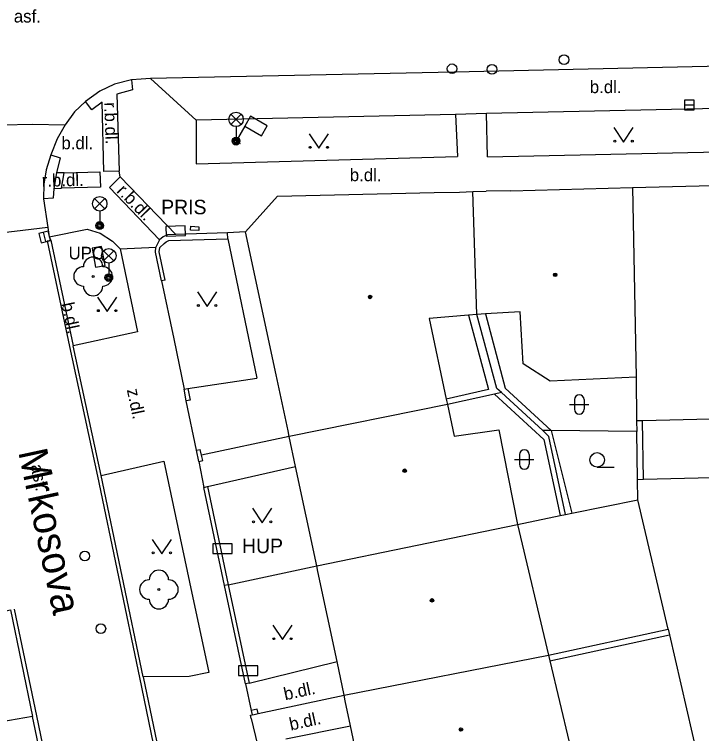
# Model space of a CAD drawing. Extents: x -596229 to -595156, y -1161237 to -1159376.
# Drawn here: x -595829.41 to -595793.88, y -1160929.68 to -1160892.51 of the extents above; entities that cross this region are included whole.
import ezdxf

# ---------------------------------------------------------------- set-up
doc = ezdxf.new("R2010")
doc.units = 0
for name, color, linetype in [('DOP - kresba z DSPS bez souradnic', 7, 'Continuous'), ('DOP - rozhrani ploch obecne', 7, 'Continuous'), ('Level 22', 7, 'Continuous'), ('Level 24', 7, 'Continuous'), ('Level 27', 7, 'Continuous'), ('Level 28', 7, 'Continuous'), ('Level 33', 7, 'Continuous'), ('Level 34', 7, 'Continuous'), ('Level 36', 7, 'Continuous'), ('Level 39', 7, 'Continuous'), ('Nazvy ulic', 7, 'Continuous'), ('silnoproud - povrch.  znaky a  RIS  skut. velikost', 7, 'Continuous'), ('slaboproud - povrch.  znaky a tel. budka skut. velikost', 7, 'Continuous'), ('Specificka linie pasportu komunikaci', 7, 'Continuous'), ('TM - budovy zdene_ betonove - VP', 7, 'Continuous'), ('TM - chodniky - VP', 7, 'Continuous'), ('TM - komunikace - VP', 7, 'Continuous'), ('TM - letecke snimky - pomocna linie', 7, 'Continuous'), ('TM - plot drateny_ kovovy - VP', 7, 'Continuous'), ('TM - podezdivka plotu - VP', 7, 'Continuous'), ('TM - pomocna konstrukcni linie', 7, 'Continuous'), ('TM - popis objektu', 7, 'Continuous'), ('TM - popis povrchu', 7, 'Continuous'), ('TM - rozhrani mezi zpev. plochami mezi sebou - VP', 7, 'Continuous'), ('TM - rozhrani ploch obecne - VP', 7, 'Continuous'), ('TM - vjezd na pozemek', 7, 'Continuous'), ('TM - vstup do budovy - zdene_ betonove', 7, 'Continuous')]:
    doc.layers.add(name, color=color, linetype=linetype)

msp = doc.modelspace()

# ---------------------------------------------------------------- linework, layer by layer
at = {"layer": 'DOP - kresba z DSPS bez souradnic'}
for points in [[(-595805.06, -1160907.99), (-595804.03, -1160911.82)], [(-595805.93, -1160908.06), (-595804.89, -1160911.89)], [(-595804.89, -1160911.89), (-595807.08, -1160912.39)], [(-595804.03, -1160911.82), (-595801.65, -1160914.02)], [(-595804.59, -1160912.13), (-595802.04, -1160914.48)], [(-595796.89, -1160916.55), (-595796.94, -1160913.51)], [(-595801.65, -1160914.02), (-595800.59, -1160918.29)], [(-595802.04, -1160914.48), (-595801.2, -1160918.41)], [(-595801.72, -1160925.91), (-595795.54, -1160924.57)]]:
    msp.add_lwpolyline(points, dxfattribs=at)
at = {"layer": 'DOP - rozhrani ploch obecne'}
for points in [[(-595804.46, -1160911.84), (-595805.5, -1160908.02)], [(-595804.23, -1160912.05), (-595804.59, -1160912.13)], [(-595804.23, -1160912.05), (-595804.46, -1160911.84)], [(-595802.09, -1160914.02), (-595804.23, -1160912.05)], [(-595804.59, -1160912.13), (-595807.02, -1160912.67)], [(-595797.24, -1160913.52), (-595797.23, -1160914.07)], [(-595801.65, -1160914.02), (-595802.09, -1160914.02)], [(-595801.77, -1160914.32), (-595802.09, -1160914.02)], [(-595800.91, -1160918.35), (-595801.77, -1160914.32)], [(-595797.23, -1160914.07), (-595801.65, -1160914.02)], [(-595797.19, -1160916.56), (-595797.23, -1160914.07)], [(-595796.89, -1160916.55), (-595797.19, -1160916.56)], [(-595797.17, -1160917.59), (-595797.19, -1160916.56)], [(-595789.82, -1160916.37), (-595796.89, -1160916.55)], [(-595800.59, -1160918.29), (-595797.17, -1160917.59)], [(-595795.61, -1160924.28), (-595797.17, -1160917.59)], [(-595803.4, -1160918.87), (-595801.2, -1160918.41)], [(-595801.2, -1160918.41), (-595800.91, -1160918.35)], [(-595800.91, -1160918.35), (-595800.59, -1160918.29)], [(-595801.79, -1160925.62), (-595795.61, -1160924.28)], [(-595795.61, -1160924.28), (-595795.54, -1160924.57)], [(-595795.54, -1160924.57), (-595794.07, -1160930.94)]]:
    msp.add_lwpolyline(points, dxfattribs=at)
at = {"layer": 'Level 22'}
for centre in [(-595825.34, -1160906.05), (-595821.94, -1160922.23)]:
    msp.add_circle(centre, 0.05, dxfattribs=at)
for centre, start, end in [((-595825.34, -1160905.55), 0, 180), ((-595825.84, -1160906.05), 90, 270), ((-595824.84, -1160906.05), 270, 90), ((-595825.34, -1160906.55), 180, 0), ((-595821.94, -1160921.73), 0, 180), ((-595822.44, -1160922.23), 90, 270), ((-595821.44, -1160922.23), 270, 90), ((-595821.94, -1160922.73), 180, 0)]:
    msp.add_arc(centre, 0.5, start, end, dxfattribs=at)
at = {"layer": 'Level 24'}
for points in [[(-595821.56, -1160903.97), (-595820.56, -1160903.93), (-595820.58, -1160903.43), (-595821.58, -1160903.47)], [(-595825.391, -1160904.585), (-595825.212, -1160905.569), (-595824.72, -1160905.48), (-595824.899, -1160904.496)], [(-595819.148, -1160920.369), (-595818.148, -1160920.369), (-595818.148, -1160919.869), (-595819.148, -1160919.869)], [(-595817.828, -1160926.669), (-595816.828, -1160926.669), (-595816.828, -1160926.169), (-595817.828, -1160926.169)]]:
    msp.add_lwpolyline(points, close=True, dxfattribs=at)
at = {"layer": 'Level 27'}
for p, q in [((-595794.76, -1160897.19), (-595794.26, -1160897.19)), ((-595827.78, -1160904.253), (-595827.9, -1160903.767))]:
    msp.add_line(p, q, dxfattribs=at)
for points in [[(-595794.76, -1160897.44), (-595794.26, -1160897.44), (-595794.26, -1160896.94), (-595794.76, -1160896.94)], [(-595827.537, -1160904.193), (-595827.657, -1160903.707), (-595828.143, -1160903.827), (-595828.023, -1160904.313)]]:
    msp.add_lwpolyline(points, close=True, dxfattribs=at)
at = {"layer": 'Level 28'}
for centre in [(-595800.99, -1160894.85), (-595806.78, -1160895.32), (-595804.72, -1160895.35), (-595825.77, -1160920.5), (-595824.94, -1160924.25)]:
    msp.add_circle(centre, 0.25, dxfattribs=at)
at = {"layer": 'Level 33'}
for p, q in [((-595818.215, -1160898.2), (-595817.685, -1160897.67)), ((-595818.215, -1160897.67), (-595817.685, -1160898.2)), ((-595817.95, -1160898.31), (-595817.95, -1160899.06)), ((-595825.265, -1160902.56), (-595824.735, -1160902.03)), ((-595825.265, -1160902.03), (-595824.735, -1160902.56)), ((-595825, -1160902.67), (-595825, -1160903.42)), ((-595824.795, -1160905.25), (-595824.265, -1160904.72)), ((-595824.795, -1160904.72), (-595824.265, -1160905.25)), ((-595824.53, -1160905.36), (-595824.53, -1160906.11))]:
    msp.add_line(p, q, dxfattribs=at)
for centre, radius in [((-595817.95, -1160897.935), 0.375), ((-595817.95, -1160899.06), 0.2), ((-595817.95, -1160899.06), 0.145), ((-595817.95, -1160899.06), 0.0876), ((-595825, -1160902.295), 0.375), ((-595825, -1160903.42), 0.2), ((-595825, -1160903.42), 0.145), ((-595825, -1160903.42), 0.0876), ((-595824.53, -1160904.985), 0.375), ((-595824.53, -1160906.11), 0.2), ((-595824.53, -1160906.11), 0.145), ((-595824.53, -1160906.11), 0.0876)]:
    msp.add_circle(centre, radius, dxfattribs=at)
at = {"layer": 'Level 34'}
for p, q in [((-595817.5, -1160898.281), (-595817.95, -1160899.06)), ((-595818.167, -1160898.935), (-595817.733, -1160899.185))]:
    msp.add_line(p, q, dxfattribs=at)
msp.add_lwpolyline([(-595817.5, -1160898.281), (-595816.634, -1160898.781), (-595816.334, -1160898.261), (-595817.2, -1160897.761)], close=True, dxfattribs=at)
at = {"layer": 'Level 36'}
for p, q in [((-595800.456, -1160912.416), (-595800.456, -1160912.916)), ((-595799.956, -1160912.416), (-595799.956, -1160912.916)), ((-595800.706, -1160912.666), (-595799.706, -1160912.666)), ((-595803.296, -1160915.256), (-595803.296, -1160915.756)), ((-595802.796, -1160915.256), (-595802.796, -1160915.756)), ((-595803.546, -1160915.506), (-595802.546, -1160915.506)), ((-595799.28, -1160915.905), (-595798.405, -1160915.905))]:
    msp.add_line(p, q, dxfattribs=at)
for points in [[(-595814.17, -1160898.68), (-595813.67, -1160899.43), (-595813.17, -1160898.68)], [(-595798.41, -1160898.36), (-595797.91, -1160899.11), (-595797.41, -1160898.36)], [(-595819.95, -1160906.85), (-595819.45, -1160907.6), (-595818.95, -1160906.85)], [(-595825.12, -1160907.12), (-595824.62, -1160907.87), (-595824.12, -1160907.12)], [(-595817.1, -1160918.03), (-595816.6, -1160918.78), (-595816.1, -1160918.03)], [(-595822.29, -1160919.64), (-595821.79, -1160920.39), (-595821.29, -1160919.64)], [(-595816.05, -1160924.07), (-595815.55, -1160924.82), (-595815.05, -1160924.07)]]:
    msp.add_lwpolyline(points, dxfattribs=at)
for centre, radius in [((-595798.36, -1160899.06), 0.05), ((-595797.461, -1160899.06), 0.05), ((-595814.12, -1160899.38), 0.05), ((-595813.221, -1160899.38), 0.05), ((-595819.9, -1160907.55), 0.05), ((-595819.001, -1160907.55), 0.05), ((-595825.07, -1160907.82), 0.05), ((-595824.171, -1160907.82), 0.05), ((-595799.28, -1160915.53), 0.375), ((-595817.05, -1160918.73), 0.05), ((-595816.151, -1160918.73), 0.05), ((-595822.24, -1160920.34), 0.05), ((-595821.341, -1160920.34), 0.05), ((-595816, -1160924.77), 0.05), ((-595815.101, -1160924.77), 0.05)]:
    msp.add_circle(centre, radius, dxfattribs=at)
for centre, start, end in [((-595800.206, -1160912.416), 0, 180), ((-595800.206, -1160912.916), 180, 0), ((-595803.046, -1160915.256), 0, 180), ((-595803.046, -1160915.756), 180, 0)]:
    msp.add_arc(centre, 0.25, start, end, dxfattribs=at)
at = {"layer": 'Level 39'}
for centre, radius in [((-595801.45, -1160905.97), 0.09), ((-595801.45, -1160905.97), 0.0398), ((-595811.02, -1160907.11), 0.09), ((-595811.02, -1160907.11), 0.0398), ((-595809.23, -1160916.09), 0.09), ((-595809.23, -1160916.09), 0.0398), ((-595807.82, -1160922.79), 0.09), ((-595807.82, -1160922.79), 0.0398), ((-595806.32, -1160929.46), 0.09), ((-595806.32, -1160929.46), 0.0398)]:
    msp.add_circle(centre, radius, dxfattribs=at)
at = {"layer": 'silnoproud - povrch.  znaky a  RIS  skut. velikost'}
for points in [[(-595816.85, -1160928.42), (-595817.16, -1160928.48)], [(-595816.8, -1160928.64), (-595816.85, -1160928.42)], [(-595817.16, -1160928.48), (-595817.11, -1160928.7)]]:
    msp.add_lwpolyline(points, dxfattribs=at)
at = {"layer": 'slaboproud - povrch.  znaky a tel. budka skut. velikost'}
msp.add_lwpolyline([(-595820.29, -1160903.46), (-595819.87, -1160903.48), (-595819.88, -1160903.68), (-595820.3, -1160903.66), (-595820.29, -1160903.46)], dxfattribs=at)
at = {"layer": 'Specificka linie pasportu komunikaci'}
for points in [[(-595826.83, -1160900.69), (-595827.24, -1160900.7)], [(-595823.94, -1160900.91), (-595824, -1160900.61)], [(-595827.38, -1160901.5), (-595826.97, -1160901.49)]]:
    msp.add_lwpolyline(points, dxfattribs=at)
at = {"layer": 'TM - budovy zdene_ betonove - VP'}
for points in [[(-595807.71, -1160901.72), (-595806.39, -1160901.69)], [(-595806.39, -1160901.69), (-595805.7, -1160901.67)], [(-595805.7, -1160901.67), (-595805.01, -1160901.65)], [(-595805.5, -1160908.02), (-595805.7, -1160901.67)], [(-595803.74, -1160901.62), (-595797.46, -1160901.46)], [(-595797.46, -1160901.46), (-595792.62, -1160901.34)], [(-595797.46, -1160901.46), (-595797.27, -1160911.25)], [(-595817.46, -1160903.75), (-595815.8, -1160901.9)], [(-595815.8, -1160901.9), (-595807.71, -1160901.72)], [(-595815.87, -1160911.14), (-595817.46, -1160903.75)], [(-595805.06, -1160907.99), (-595805.5, -1160908.02)], [(-595803.26, -1160907.88), (-595805.06, -1160907.99)], [(-595803.1, -1160910.57), (-595803.26, -1160907.88)], [(-595805.93, -1160908.06), (-595807.96, -1160908.22)], [(-595807.96, -1160908.22), (-595807.08, -1160912.39)], [(-595805.5, -1160908.02), (-595805.93, -1160908.06)], [(-595801.71, -1160911.46), (-595803.1, -1160910.57)], [(-595815.26, -1160914.03), (-595815.87, -1160911.14)], [(-595797.27, -1160911.25), (-595801.71, -1160911.46)], [(-595797.27, -1160911.25), (-595797.24, -1160913.52)], [(-595807.08, -1160912.39), (-595807.02, -1160912.67)], [(-595807.02, -1160912.67), (-595815.2, -1160914.32)], [(-595807.02, -1160912.67), (-595806.67, -1160914.3)], [(-595796.94, -1160913.51), (-595797.24, -1160913.52)], [(-595789.91, -1160913.34), (-595796.94, -1160913.51)], [(-595815.2, -1160914.32), (-595815.26, -1160914.03)], [(-595814.87, -1160915.88), (-595815.2, -1160914.32)], [(-595806.67, -1160914.3), (-595804.36, -1160913.97)], [(-595804.36, -1160913.97), (-595803.4, -1160918.87)], [(-595813.78, -1160921), (-595814.87, -1160915.88)], [(-595813.78, -1160921), (-595803.4, -1160918.87)], [(-595803.4, -1160918.87), (-595801.79, -1160925.62)], [(-595813.72, -1160921.3), (-595813.78, -1160921)], [(-595812.73, -1160925.95), (-595813.72, -1160921.3)], [(-595812.36, -1160927.69), (-595801.79, -1160925.62)], [(-595801.79, -1160925.62), (-595801.72, -1160925.91)], [(-595812.36, -1160927.69), (-595812.73, -1160925.95)], [(-595801.72, -1160925.91), (-595800.22, -1160932.22)], [(-595812.3, -1160927.98), (-595812.36, -1160927.69)], [(-595812.03, -1160929.28), (-595812.3, -1160927.98)], [(-595811.67, -1160931), (-595812.03, -1160929.28)]]:
    msp.add_lwpolyline(points, dxfattribs=at)
at = {"layer": 'TM - chodniky - VP'}
for points in [[(-595804.95, -1160899.87), (-595792.99, -1160899.62), (-595793.04, -1160897.38)], [(-595820.01, -1160897.98), (-595820.02, -1160900.24), (-595806.5, -1160899.85)], [(-595806.61, -1160897.68), (-595806.5, -1160899.85)], [(-595804.95, -1160899.87), (-595805, -1160897.64)], [(-595827.61, -1160904.01), (-595825.65, -1160903.6), (-595824.97, -1160903.82), (-595824.34, -1160904.23), (-595823.95, -1160904.63)], [(-595823.95, -1160904.63), (-595823.04, -1160908.92), (-595826.37, -1160909.63)], [(-595824.92, -1160916.34), (-595821.68, -1160915.6), (-595820.36, -1160921.85), (-595819.36, -1160926.51)], [(-595817.27, -1160927.07), (-595812.73, -1160925.95)], [(-595819.36, -1160926.51), (-595820.38, -1160926.72), (-595822.75, -1160926.74)], [(-595815.37, -1160929.95), (-595812.03, -1160929.28)]]:
    msp.add_lwpolyline(points, dxfattribs=at)
at = {"layer": 'TM - komunikace - VP'}
for points in [[(-595823.35, -1160895.89), (-595824.24, -1160896.12), (-595824.99, -1160896.48), (-595825.73, -1160897.02)], [(-595822.38, -1160895.83), (-595822.86, -1160895.85), (-595823.35, -1160895.89)], [(-595820.01, -1160897.98), (-595822.38, -1160895.83)], [(-595825.73, -1160897.02), (-595826.3, -1160897.54), (-595826.78, -1160898.21)], [(-595793.04, -1160897.38), (-595805, -1160897.64)], [(-595806.61, -1160897.68), (-595820.01, -1160897.98)], [(-595805, -1160897.64), (-595806.61, -1160897.68)], [(-595826.78, -1160898.21), (-595827.2, -1160898.94), (-595827.52, -1160899.76)], [(-595827.52, -1160899.76), (-595827.76, -1160900.55), (-595827.88, -1160901.28), (-595827.9, -1160902.04)], [(-595827.9, -1160902.04), (-595827.69, -1160903.53)], [(-595827.69, -1160903.53), (-595827.61, -1160904.01)], [(-595827.61, -1160904.01), (-595827.52, -1160904.17)], [(-595827.52, -1160904.17), (-595826.37, -1160909.63)], [(-595824.92, -1160916.34), (-595826.37, -1160909.63)], [(-595822.75, -1160926.74), (-595824.92, -1160916.34)], [(-595828.47, -1160928.79), (-595831.67, -1160929.34), (-595832.76, -1160923.95), (-595829.62, -1160923.28)], [(-595829.62, -1160923.28), (-595828.47, -1160928.79)], [(-595822.75, -1160926.74), (-595820.84, -1160935.93)], [(-595827.15, -1160935.12), (-595828.47, -1160928.79)]]:
    msp.add_lwpolyline(points, dxfattribs=at)
at = {"layer": 'TM - letecke snimky - pomocna linie'}
for points in [[(-595818.38, -1160904.1), (-595816.87, -1160911.3)], [(-595820.44, -1160911.84), (-595816.87, -1160911.3)], [(-595819.42, -1160916.91), (-595814.87, -1160915.88)]]:
    msp.add_lwpolyline(points, dxfattribs=at)
at = {"layer": 'TM - plot drateny_ kovovy - VP'}
for points in [[(-595818.38, -1160904.1), (-595818.39, -1160903.8)], [(-595821.89, -1160904.56), (-595821.67, -1160904.35), (-595821.56, -1160904.27), (-595821.43, -1160904.2), (-595818.38, -1160904.1)], [(-595821.61, -1160906.24), (-595821.92, -1160904.78), (-595821.89, -1160904.56)], [(-595820.44, -1160911.84), (-595820.33, -1160912.44)], [(-595815.2, -1160914.32), (-595819.74, -1160915.28)], [(-595819.74, -1160915.28), (-595819.8, -1160914.99)], [(-595819.67, -1160915.57), (-595819.74, -1160915.28)], [(-595819.42, -1160916.91), (-595818.35, -1160921.98)], [(-595818.35, -1160921.98), (-595813.78, -1160921)], [(-595818.35, -1160921.98), (-595817.27, -1160927.07)], [(-595816.8, -1160928.64), (-595812.36, -1160927.69)], [(-595817.01, -1160928.68), (-595816.8, -1160928.64)]]:
    msp.add_lwpolyline(points, dxfattribs=at)
at = {"layer": 'TM - podezdivka plotu - VP'}
for points in [[(-595821.07, -1160903.89), (-595821.49, -1160903.9), (-595821.71, -1160904), (-595821.9, -1160904.16)], [(-595818.39, -1160903.8), (-595821.07, -1160903.89)], [(-595821.9, -1160904.16), (-595822.09, -1160904.54)], [(-595821.81, -1160906.28), (-595822.12, -1160904.79), (-595822.09, -1160904.54)], [(-595821.61, -1160906.24), (-595821.81, -1160906.28)], [(-595820.64, -1160911.88), (-595820.44, -1160911.84)], [(-595820.53, -1160912.48), (-595820.64, -1160911.88)], [(-595820.33, -1160912.44), (-595820.53, -1160912.48)], [(-595820, -1160915.03), (-595819.8, -1160914.99)], [(-595819.87, -1160915.61), (-595820, -1160915.03)], [(-595819.87, -1160915.61), (-595819.67, -1160915.57)], [(-595819.62, -1160916.95), (-595819.42, -1160916.91)], [(-595818.55, -1160922.02), (-595819.62, -1160916.95)], [(-595818.35, -1160921.98), (-595818.55, -1160922.02)], [(-595817.47, -1160927.11), (-595818.55, -1160922.02)], [(-595817.27, -1160927.07), (-595817.47, -1160927.11)], [(-595817.17, -1160928.89), (-595817.21, -1160928.73), (-595817.11, -1160928.7)], [(-595817.11, -1160928.7), (-595817.01, -1160928.68)]]:
    msp.add_lwpolyline(points, dxfattribs=at)
at = {"layer": 'TM - pomocna konstrukcni linie'}
msp.add_lwpolyline([(-595827.72, -1160904.21), (-595827.52, -1160904.17)], dxfattribs=at)
at = {"layer": 'TM - rozhrani mezi zpev. plochami mezi sebou - VP'}
for points in [[(-595823.35, -1160895.89), (-595823.3, -1160896.41), (-595824.12, -1160896.63), (-595824, -1160900.61)], [(-595824, -1160900.61), (-595824.79, -1160900.63), (-595824.87, -1160897.04), (-595825.4, -1160897.45), (-595825.73, -1160897.02)], [(-595836.17, -1160898.36), (-595828.5, -1160898.18), (-595826.78, -1160898.21)], [(-595827.52, -1160899.76), (-595827.04, -1160899.92), (-595827.24, -1160900.7)], [(-595827.24, -1160900.7), (-595827.38, -1160901.5)], [(-595825, -1160900.64), (-595824.96, -1160901.43), (-595826.97, -1160901.49)], [(-595826.97, -1160901.49), (-595826.83, -1160900.69)], [(-595826.83, -1160900.69), (-595825, -1160900.64)], [(-595823.94, -1160900.91), (-595824.5, -1160901.46), (-595821.9, -1160904.16)], [(-595821.07, -1160903.89), (-595823.94, -1160900.91)], [(-595827.38, -1160901.5), (-595827.41, -1160902.01), (-595827.9, -1160902.04)], [(-595827.69, -1160903.53), (-595833.46, -1160904.21)], [(-595827.72, -1160904.21), (-595826.57, -1160909.67), (-595825.12, -1160916.38), (-595822.95, -1160926.78)], [(-595823.95, -1160904.63), (-595822.09, -1160904.54)], [(-595829.42, -1160923.24), (-595828.27, -1160928.75), (-595826.95, -1160935.08), (-595825.6, -1160941.55), (-595823.16, -1160953.04), (-595821.46, -1160961.17), (-595821.06, -1160963.13)], [(-595822.95, -1160926.78), (-595821.04, -1160935.97), (-595818.72, -1160946.95), (-595817.48, -1160952.83), (-595815.29, -1160963.27)], [(-595817.47, -1160927.11), (-595817.16, -1160928.48)]]:
    msp.add_lwpolyline(points, dxfattribs=at)
at = {"layer": 'TM - rozhrani ploch obecne - VP'}
msp.add_lwpolyline([(-595640.97, -1160891.77), (-595650.48, -1160891.96), (-595666.97, -1160892.33), (-595687.37, -1160892.8), (-595707.59, -1160893.25), (-595726.73, -1160893.7), (-595744.06, -1160894.1), (-595769.01, -1160894.68), (-595788.98, -1160895.1), (-595806.67, -1160895.5), (-595822.38, -1160895.83)], dxfattribs=at)
at = {"layer": 'TM - vjezd na pozemek'}
for points in [[(-595817.46, -1160903.75), (-595818.39, -1160903.8)], [(-595821.81, -1160906.28), (-595821.16, -1160909.27)], [(-595821.16, -1160909.27), (-595820.64, -1160911.88)], [(-595820, -1160915.03), (-595820.53, -1160912.48)], [(-595819.87, -1160915.61), (-595819.62, -1160916.95)], [(-595817.17, -1160928.89), (-595816.84, -1160930.25)]]:
    msp.add_lwpolyline(points, dxfattribs=at)
at = {"layer": 'TM - vstup do budovy - zdene_ betonove'}
msp.add_lwpolyline([(-595803.74, -1160901.62), (-595805.01, -1160901.65)], dxfattribs=at)

# ---------------------------------------------------------------- texts
at = {"layer": 'Nazvy ulic'}
msp.add_text('Mrkosova', height=1.5, rotation=282.1577, dxfattribs=at).set_placement((-595829.219, -1160915.11))
at = {"layer": 'TM - popis objektu'}
for s, height, p in [('PRIS', 0.75, (-595821.82, -1160902.84)), ('UPC', 0.65, (-595826.61, -1160905.17)), ('HUP', 0.75, (-595817.64, -1160920.35))]:
    msp.add_text(s, height=height, dxfattribs=at).set_placement(p)
at = {"layer": 'TM - popis povrchu'}
for s, p in [('asf.', (-595829.44, -1160892.93)), ('b.dl.', (-595799.66, -1160896.58)), ('b.dl.', (-595826.98, -1160899.48)), ('b.dl.', (-595812.07, -1160901.13))]:
    msp.add_text(s, height=0.65, dxfattribs=at).set_placement(p)
for s, rotation, p in [('r.b.dl.', 272.09, (-595824.77, -1160897.06)), ('r.b.dl.', 1.39, (-595827.99, -1160901.42)), ('r.b.dl.', 314.27, (-595824.16, -1160901.67)), ('b.dl.', 281.8472, (-595826.98, -1160907.46)), ('z.dl.', 281.8472, (-595823.6, -1160911.91)), ('asf.', 282, (-595828.58, -1160915.82)), ('b.dl.', 12.3027, (-595815.41, -1160927.96)), ('b.dl.', 12.3027, (-595815.12, -1160929.52))]:
    msp.add_text(s, height=0.65, rotation=rotation, dxfattribs=at).set_placement(p)

doc.saveas('drawing.dxf')
